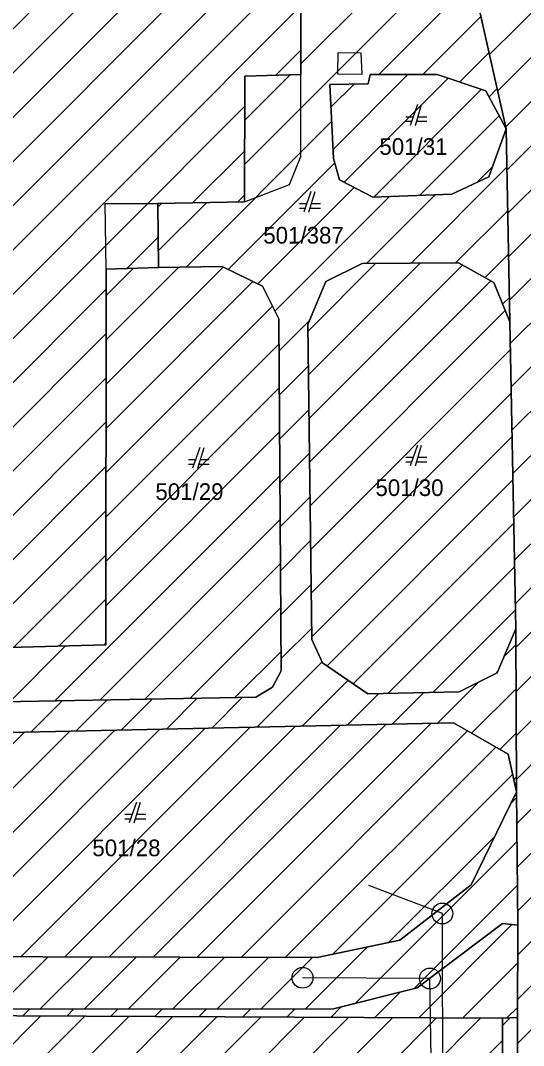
# Model space of a CAD drawing. Extents: x -264309 to -263505, y -1242443 to -1241763.
# Drawn here: x -263997.1 to -263948.8, y -1242199.4 to -1242101 of the extents above; entities that cross this region are included whole.
import ezdxf

# ---------------------------------------------------------------- set-up
doc = ezdxf.new("R2010")
doc.units = 0
for name, color, linetype in [('KFA_DAZDOVA_KANALIZACIA_vetva_H', 7, 'Continuous'), ('KFA_SPLASKOVA_KANALIZACIA_SO-40-1-II', 7, 'Continuous'), ('KN_2019_08_16_KLADPAR', 7, 'Continuous'), ('KN_2019_08_16_ZAPPAR', 7, 'Continuous'), ('SRAFY_PARCELY', 7, 'Continuous')]:
    doc.layers.add(name, color=color, linetype=linetype)

msp = doc.modelspace()

# ---------------------------------------------------------------- linework, layer by layer
at = {"layer": 'KFA_DAZDOVA_KANALIZACIA_vetva_H'}
msp.add_lwpolyline([(-263956.104, -1242251.541), (-263956.553, -1242222.652), (-263956.616, -1242186.719), (-263963.661, -1242184.028)], dxfattribs=at)
msp.add_circle((-263956.616, -1242186.719), 1, dxfattribs=at)
at = {"layer": 'KFA_SPLASKOVA_KANALIZACIA_SO-40-1-II'}
msp.add_lwpolyline([(-263956.969, -1242244.288), (-263957.81, -1242192.95), (-263970.042, -1242192.883)], dxfattribs=at)
for centre in [(-263970.042, -1242192.883), (-263957.81, -1242192.95)]:
    msp.add_circle(centre, 1, dxfattribs=at)
at = {"layer": 'KN_2019_08_16_KLADPAR'}
for p, q in [((-263959.01, -1242109.1), (-263959.71, -1242111.1)), ((-263959.21, -1242111.1), (-263958.61, -1242109.1)), ((-263959.43, -1242110.3), (-263960.11, -1242110.3)), ((-263960.11, -1242110.7), (-263959.57, -1242110.7)), ((-263959.09, -1242110.7), (-263958.11, -1242110.7)), ((-263958.11, -1242110.3), (-263958.97, -1242110.3)), ((-263969.23, -1242117.44), (-263969.93, -1242119.44)), ((-263969.43, -1242119.44), (-263968.83, -1242117.44)), ((-263969.65, -1242118.64), (-263970.33, -1242118.64)), ((-263968.33, -1242118.64), (-263969.19, -1242118.64)), ((-263970.33, -1242119.04), (-263969.79, -1242119.04)), ((-263969.31, -1242119.04), (-263968.33, -1242119.04)), ((-263979.9, -1242141.99), (-263980.6, -1242143.99)), ((-263980.1, -1242143.99), (-263979.5, -1242141.99)), ((-263959.01, -1242141.77), (-263959.71, -1242143.77)), ((-263959.21, -1242143.77), (-263958.61, -1242141.77)), ((-263980.32, -1242143.19), (-263981, -1242143.19)), ((-263979, -1242143.19), (-263979.86, -1242143.19)), ((-263959.43, -1242142.97), (-263960.11, -1242142.97)), ((-263958.11, -1242142.97), (-263958.97, -1242142.97)), ((-263981, -1242143.59), (-263980.46, -1242143.59)), ((-263979.98, -1242143.59), (-263979, -1242143.59)), ((-263960.11, -1242143.37), (-263959.57, -1242143.37)), ((-263959.09, -1242143.37), (-263958.11, -1242143.37)), ((-263985.99, -1242176.03), (-263986.69, -1242178.03)), ((-263986.19, -1242178.03), (-263985.59, -1242176.03)), ((-263986.41, -1242177.23), (-263987.09, -1242177.23)), ((-263987.09, -1242177.63), (-263986.55, -1242177.63)), ((-263986.07, -1242177.63), (-263985.09, -1242177.63)), ((-263985.09, -1242177.23), (-263985.95, -1242177.23))]:
    msp.add_line(p, q, dxfattribs=at)
for points in [[(-263945.92, -1242287.35), (-263949.74, -1242287.63), (-263949.41, -1242196.68), (-263949.38, -1242187.85), (-263949.49, -1242175.05), (-263949.55, -1242159.39), (-263950.14, -1242129.96), (-263950.48, -1242111.43), (-263955.8, -1242087.79), (-263956.24, -1242069.24), (-263949.96, -1242070.83), (-263947.13, -1242072.33), (-263942.68, -1242071.91), (-263941.47, -1242124.08), (-263944.59, -1242125.87), (-263946.11, -1242129.79), (-263945.51, -1242159.3), (-263945.41, -1242187.87)], [(-263952.44, -1242107.8), (-263950.48, -1242111.43), (-263952.14, -1242116.04), (-263955.72, -1242117.71), (-263963.29, -1242117.98), (-263966.5, -1242116.32), (-263967.07, -1242114.27), (-263967.42, -1242107.18), (-263963.73, -1242107.11), (-263963.54, -1242106.22), (-263957.1, -1242106.21)], [(-263950.14, -1242129.96), (-263949.55, -1242159.39), (-263951.34, -1242163.61), (-263955.01, -1242165.46), (-263963.77, -1242165.63), (-263968.11, -1242162.65), (-263969.15, -1242160.43), (-263969.52, -1242130.2), (-263967.79, -1242126.09), (-263964.33, -1242124.35), (-263955.07, -1242124.29), (-263951.68, -1242126.19)], [(-263988.88, -1242124.89), (-263983.88, -1242124.73), (-263977.77, -1242124.63), (-263973.88, -1242126.53), (-263972.33, -1242129.65), (-263972.09, -1242163.43), (-263972.93, -1242164.99), (-263974.51, -1242165.96), (-264000.63, -1242166.44), (-264001.62, -1242165.72), (-264001.73, -1242161.29), (-263988.91, -1242160.93)], [(-264070.8, -1242196.19), (-264074.04, -1242162.41), (-264076.3, -1242133.7), (-264076.98, -1242129.46), (-264073.21, -1242136.9), (-264064.2, -1242141.11), (-264053.9, -1242149.28), (-264045.08, -1242172.51), (-264039.7, -1242185.21), (-264028.16, -1242194.26), (-264020.26, -1242195.89), (-263967.07, -1242195.86), (-263959.05, -1242193.86), (-263950.83, -1242187.66), (-263949.38, -1242187.85), (-263949.41, -1242196.68), (-263950.84, -1242196.76)], [(-263950.84, -1242196.76), (-263951.29, -1242290.6), (-263951.37, -1242306.76), (-264045.86, -1242306.31), (-264099.36, -1242306.05), (-264098.84, -1242196.05), (-264070.8, -1242196.19)], [(-263951.29, -1242290.6), (-263950.84, -1242196.76), (-263949.41, -1242196.68), (-263949.74, -1242287.63)]]:
    msp.add_lwpolyline(points, close=True, dxfattribs=at)
for points in [[(-263955.8, -1242087.79), (-263950.48, -1242111.43), (-263952.44, -1242107.8), (-263957.1, -1242106.21), (-263963.54, -1242106.22), (-263963.73, -1242107.11), (-263967.42, -1242107.18), (-263967.07, -1242114.27), (-263966.5, -1242116.32), (-263963.29, -1242117.98), (-263955.72, -1242117.71), (-263952.14, -1242116.04), (-263950.48, -1242111.43), (-263950.14, -1242129.96), (-263951.68, -1242126.19), (-263955.07, -1242124.29), (-263964.33, -1242124.35), (-263967.79, -1242126.09), (-263969.52, -1242130.2), (-263969.15, -1242160.43), (-263968.11, -1242162.65), (-263963.77, -1242165.63), (-263955.01, -1242165.46), (-263951.34, -1242163.61), (-263949.55, -1242159.39), (-263949.49, -1242175.05), (-263950.29, -1242171.43), (-263955.56, -1242168.43), (-264001.16, -1242169.4)], [(-263970.24, -1242093.63), (-263970.22, -1242106.22), (-263975.57, -1242106.38), (-263975.61, -1242118.44), (-263983.93, -1242118.61), (-263983.88, -1242124.73), (-263988.88, -1242124.89), (-263988.91, -1242160.93), (-264001.73, -1242161.29)], [(-264000.63, -1242166.44), (-263974.51, -1242165.96), (-263972.93, -1242164.99), (-263972.09, -1242163.43), (-263972.33, -1242129.65), (-263973.88, -1242126.53), (-263977.77, -1242124.63), (-263983.88, -1242124.73), (-263983.93, -1242118.61), (-263975.61, -1242118.44), (-263975.57, -1242106.38), (-263970.22, -1242106.22), (-263970.24, -1242093.63)], [(-264001.16, -1242169.4), (-263955.56, -1242168.43), (-263950.29, -1242171.43), (-263949.49, -1242175.05), (-263953.85, -1242183.98), (-263960.7, -1242189.28), (-263968.63, -1242190.95), (-264021.34, -1242190.81)], [(-264021.34, -1242190.81), (-263968.63, -1242190.95), (-263960.7, -1242189.28), (-263953.85, -1242183.98), (-263949.49, -1242175.05), (-263949.38, -1242187.85), (-263950.83, -1242187.66), (-263959.05, -1242193.86), (-263967.07, -1242195.86), (-264020.26, -1242195.89)]]:
    msp.add_lwpolyline(points, dxfattribs=at)
at = {"layer": 'KN_2019_08_16_ZAPPAR'}
for p, q in [((-263966.66, -1242104.14), (-263966.68, -1242106.17)), ((-263970.21, -1242114.1), (-263970.22, -1242106.22)), ((-263988.88, -1242124.89), (-263989, -1242118.61)), ((-263989, -1242118.61), (-263983.93, -1242118.61))]:
    msp.add_line(p, q, dxfattribs=at)
for points in [[(-263966.68, -1242106.17), (-263964.32, -1242106.19), (-263964.41, -1242104.16), (-263966.66, -1242104.14)], [(-263975.61, -1242118.44), (-263971.29, -1242116.78), (-263970.21, -1242114.1)]]:
    msp.add_lwpolyline(points, dxfattribs=at)
at = {"layer": 'SRAFY_PARCELY'}
for p, q in [((-264018.49, -1242122.481), (-263977.519, -1242081.51)), ((-264016.478, -1242124.712), (-263975.759, -1242083.993)), ((-264016.475, -1242128.951), (-263975.725, -1242088.201)), ((-263970.222, -1242105.229), (-263955.246, -1242090.253)), ((-264016.472, -1242133.191), (-263975.69, -1242092.409)), ((-264016.441, -1242137.403), (-263972.66, -1242093.621)), ((-263975.598, -1242114.848), (-263954.466, -1242093.716)), ((-263952.081, -1242104.315), (-263942.159, -1242094.392)), ((-264027.478, -1242152.682), (-263970.237, -1242095.441)), ((-263962.726, -1242106.219), (-263953.687, -1242097.18)), ((-263951.302, -1242107.778), (-263942.062, -1242098.538)), ((-264027.444, -1242156.891), (-263970.23, -1242099.677)), ((-263958.477, -1242106.212), (-263952.908, -1242100.643)), ((-263950.523, -1242111.241), (-263941.966, -1242102.685)), ((-263972.602, -1242106.291), (-263970.224, -1242103.913)), ((-263954.962, -1242106.94), (-263952.128, -1242104.106)), ((-263975.584, -1242110.591), (-263971.243, -1242106.251)), ((-263967.113, -1242113.398), (-263959.93, -1242106.214)), ((-263966.034, -1242116.561), (-263956.043, -1242106.571)), ((-263950.408, -1242115.369), (-263941.87, -1242106.831)), ((-263967.313, -1242109.355), (-263965.094, -1242107.136)), ((-263963.207, -1242117.977), (-263952.88, -1242107.65)), ((-263952.138, -1242108.359), (-263951.349, -1242107.569)), ((-264027.028, -1242160.717), (-263975.58, -1242109.269)), ((-263981.193, -1242124.686), (-263967.244, -1242110.737)), ((-263958.808, -1242117.82), (-263951.159, -1242110.172)), ((-263950.651, -1242111.114), (-263950.569, -1242111.033)), ((-263950.331, -1242119.535), (-263941.774, -1242110.978)), ((-263980.61, -1242118.542), (-263975.594, -1242113.526)), ((-263977.182, -1242124.917), (-263966.954, -1242114.689)), ((-263959.614, -1242124.319), (-263950.412, -1242115.118)), ((-263953.349, -1242116.604), (-263951.777, -1242115.032)), ((-263950.255, -1242123.701), (-263941.678, -1242115.124)), ((-263974.332, -1242126.309), (-263965.078, -1242117.056)), ((-263983.927, -1242118.935), (-263983.596, -1242118.603)), ((-263983.893, -1242123.143), (-263979.265, -1242118.515)), ((-263976.279, -1242118.454), (-263975.608, -1242117.782)), ((-263972.695, -1242128.915), (-263961.703, -1242117.923)), ((-263963.884, -1242124.347), (-263957.303, -1242117.766)), ((-263955.343, -1242124.292), (-263950.336, -1242119.284)), ((-263950.178, -1242127.868), (-263941.582, -1242119.271)), ((-263986.895, -1242124.826), (-263983.904, -1242121.836)), ((-263952.525, -1242125.716), (-263950.259, -1242123.451)), ((-263969.512, -1242130.83), (-263963.024, -1242124.342)), ((-263969.461, -1242135.021), (-263958.754, -1242124.314)), ((-263969.41, -1242139.213), (-263954.696, -1242124.499)), ((-263988.889, -1242135.926), (-263977.651, -1242124.688)), ((-263988.886, -1242131.68), (-263981.903, -1242124.698)), ((-263988.882, -1242127.434), (-263986.254, -1242124.806)), ((-263988.893, -1242140.173), (-263974.801, -1242126.08)), ((-263969.358, -1242143.404), (-263951.978, -1242126.023)), ((-264027.378, -1242165.31), (-263988.882, -1242126.814)), ((-263950.098, -1242132.03), (-263945.003, -1242126.935)), ((-263988.896, -1242144.419), (-263972.927, -1242128.449)), ((-263950.832, -1242128.266), (-263950.183, -1242127.617)), ((-263969.307, -1242147.595), (-263950.584, -1242128.872)), ((-263972.308, -1242132.771), (-263969.362, -1242129.826)), ((-264026.703, -1242168.877), (-263988.885, -1242131.06)), ((-263988.9, -1242148.665), (-263972.313, -1242132.078)), ((-263950.015, -1242136.19), (-263946.06, -1242132.235)), ((-263969.256, -1242151.787), (-263950.087, -1242132.618)), ((-263972.278, -1242136.984), (-263969.471, -1242134.177)), ((-264027.314, -1242173.731), (-263988.889, -1242135.306)), ((-263988.903, -1242152.911), (-263972.283, -1242136.291)), ((-263969.204, -1242155.978), (-263950.003, -1242136.777)), ((-263949.932, -1242140.349), (-263945.976, -1242136.393)), ((-263972.248, -1242141.196), (-263969.42, -1242138.368)), ((-264004.287, -1242154.947), (-263988.892, -1242139.552)), ((-263988.907, -1242157.157), (-263972.253, -1242140.503)), ((-263969.153, -1242160.169), (-263949.92, -1242140.936)), ((-263949.848, -1242144.508), (-263945.891, -1242140.551)), ((-263972.218, -1242145.409), (-263969.369, -1242142.56)), ((-264001.781, -1242156.683), (-263988.896, -1242143.798)), ((-263993.822, -1242166.315), (-263972.223, -1242144.716)), ((-263967.684, -1242162.943), (-263949.837, -1242145.095)), ((-263949.765, -1242148.667), (-263945.807, -1242144.709)), ((-263972.188, -1242149.622), (-263969.317, -1242146.751)), ((-264001.735, -1242160.88), (-263988.899, -1242148.044)), ((-263989.5, -1242166.235), (-263972.193, -1242148.929)), ((-263949.682, -1242152.827), (-263945.722, -1242148.867)), ((-263965.168, -1242164.67), (-263949.753, -1242149.255)), ((-263972.158, -1242153.835), (-263969.266, -1242150.942)), ((-263997.792, -1242161.179), (-263988.903, -1242152.291)), ((-263949.598, -1242156.986), (-263945.638, -1242153.025)), ((-263985.178, -1242166.156), (-263972.163, -1242153.141)), ((-263961.849, -1242165.593), (-263949.67, -1242153.414)), ((-263972.128, -1242158.047), (-263969.215, -1242155.134)), ((-263993.426, -1242161.057), (-263988.906, -1242156.537)), ((-263980.856, -1242166.077), (-263972.133, -1242157.354)), ((-263957.522, -1242165.509), (-263949.586, -1242157.573)), ((-263949.543, -1242161.173), (-263945.553, -1242157.183)), ((-263972.098, -1242162.26), (-263969.164, -1242159.325)), ((-263989.061, -1242160.934), (-263988.91, -1242160.783)), ((-263950.681, -1242162.055), (-263949.544, -1242160.919)), ((-263998.144, -1242166.394), (-263992.789, -1242161.039)), ((-263976.534, -1242165.997), (-263972.103, -1242161.567)), ((-263949.527, -1242165.4), (-263945.503, -1242161.376)), ((-263974.427, -1242168.831), (-263968.153, -1242162.558)), ((-263951.422, -1242163.651), (-263951.31, -1242163.539)), ((-263970.092, -1242168.739), (-263965.675, -1242164.322)), ((-263957.088, -1242168.462), (-263953.145, -1242164.52)), ((-263965.757, -1242168.647), (-263962.72, -1242165.61)), ((-263961.423, -1242168.555), (-263958.393, -1242165.526)), ((-263953.809, -1242169.427), (-263949.528, -1242165.145)), ((-263949.511, -1242169.626), (-263945.488, -1242165.603)), ((-263996.101, -1242169.292), (-263993.111, -1242166.302)), ((-263991.766, -1242169.2), (-263988.789, -1242166.222)), ((-263987.432, -1242169.108), (-263984.467, -1242166.143)), ((-263983.097, -1242169.016), (-263980.145, -1242166.064)), ((-263978.762, -1242168.924), (-263975.822, -1242165.984)), ((-263992.854, -1242190.886), (-263970.721, -1242168.753)), ((-263988.623, -1242190.897), (-263966.386, -1242168.66)), ((-263984.391, -1242190.908), (-263962.051, -1242168.568)), ((-263980.16, -1242190.919), (-263957.717, -1242168.476)), ((-264018.243, -1242190.818), (-263996.73, -1242169.306)), ((-264014.011, -1242190.829), (-263992.395, -1242169.214)), ((-264009.78, -1242190.841), (-263988.06, -1242169.121)), ((-264005.548, -1242190.852), (-263983.726, -1242169.029)), ((-264001.317, -1242190.863), (-263979.391, -1242168.937)), ((-263997.086, -1242190.874), (-263975.056, -1242168.845)), ((-263975.929, -1242190.931), (-263954.201, -1242169.203)), ((-263951.106, -1242170.966), (-263949.512, -1242169.372)), ((-263971.697, -1242190.942), (-263951.498, -1242170.742)), ((-263949.495, -1242173.853), (-263945.473, -1242169.831)), ((-263967.151, -1242190.639), (-263949.865, -1242173.352)), ((-263949.754, -1242173.857), (-263949.496, -1242173.598)), ((-263949.464, -1242178.065), (-263945.458, -1242174.059)), ((-263950.011, -1242176.117), (-263949.485, -1242175.592)), ((-263949.428, -1242182.271), (-263945.444, -1242178.287)), ((-263961.777, -1242189.507), (-263951.56, -1242179.29)), ((-263964.993, -1242195.342), (-263949.449, -1242179.798)), ((-263949.392, -1242186.478), (-263945.429, -1242182.515)), ((-263959.341, -1242193.933), (-263949.413, -1242184.004)), ((-263949.39, -1242190.718), (-263945.414, -1242186.743)), ((-263958.89, -1242196.722), (-263949.944, -1242187.776)), ((-263969.755, -1242195.862), (-263963.834, -1242189.94)), ((-263999.471, -1242195.878), (-263994.474, -1242190.881)), ((-263995.226, -1242195.876), (-263990.242, -1242190.893)), ((-263990.981, -1242195.873), (-263986.011, -1242190.904)), ((-263986.735, -1242195.871), (-263981.779, -1242190.915)), ((-263982.49, -1242195.869), (-263977.548, -1242190.926)), ((-263978.245, -1242195.866), (-263973.317, -1242190.938)), ((-263974, -1242195.864), (-263969.085, -1242190.949)), ((-263949.404, -1242194.976), (-263945.426, -1242190.997)), ((-263954.667, -1242196.742), (-263949.392, -1242191.467)), ((-263963.112, -1242196.702), (-263960.676, -1242194.266)), ((-263949.419, -1242199.233), (-263945.448, -1242195.262)), ((-263996.893, -1242196.541), (-263996.228, -1242195.876)), ((-263992.67, -1242196.561), (-263991.983, -1242195.874)), ((-263988.448, -1242196.581), (-263987.738, -1242195.872)), ((-263984.225, -1242196.601), (-263983.493, -1242195.869)), ((-263980.003, -1242196.621), (-263979.248, -1242195.867)), ((-263975.78, -1242196.641), (-263975.003, -1242195.864)), ((-263971.558, -1242196.662), (-263970.758, -1242195.862)), ((-263967.335, -1242196.682), (-263966.328, -1242195.675)), ((-263950.419, -1242196.736), (-263949.407, -1242195.724)), ((-264099.355, -1242304.975), (-263990.95, -1242196.569)), ((-264099.335, -1242300.712), (-263995.172, -1242196.549)), ((-264096.203, -1242306.065), (-263986.727, -1242196.589)), ((-264091.981, -1242306.086), (-263982.504, -1242196.61)), ((-264087.759, -1242306.106), (-263978.282, -1242196.63)), ((-264083.537, -1242306.127), (-263974.059, -1242196.65)), ((-264079.314, -1242306.147), (-263969.837, -1242196.67)), ((-264075.092, -1242306.168), (-263965.614, -1242196.69)), ((-264070.87, -1242306.188), (-263961.392, -1242196.71)), ((-264066.648, -1242306.209), (-263957.169, -1242196.73)), ((-264062.426, -1242306.229), (-263952.946, -1242196.75)), ((-263950.843, -1242197.456), (-263950.107, -1242196.719)), ((-264058.204, -1242306.25), (-263950.85, -1242198.896))]:
    msp.add_line(p, q, dxfattribs=at)

# ---------------------------------------------------------------- texts
at = {"layer": 'KN_2019_08_16_KLADPAR'}
for s, p in [('501/31', (-263962.662, -1242113.93)), ('501/387', (-263973.811, -1242122.44)), ('501/30', (-263963.043, -1242146.66)), ('501/29', (-263984.169, -1242147.04)), ('501/28', (-263990.219, -1242181.22))]:
    msp.add_text(s, height=1.6, dxfattribs=at).set_placement(p)

doc.saveas('drawing.dxf')
